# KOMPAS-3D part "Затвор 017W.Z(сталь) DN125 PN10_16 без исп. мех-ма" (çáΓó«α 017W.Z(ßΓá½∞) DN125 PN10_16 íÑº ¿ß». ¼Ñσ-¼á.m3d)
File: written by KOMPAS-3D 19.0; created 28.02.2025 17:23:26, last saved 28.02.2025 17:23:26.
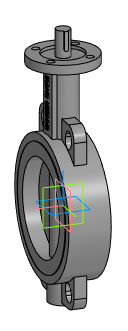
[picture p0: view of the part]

Document properties: Автор: Евгений; Полное имя файла: E:\Dendor Работа Сачек\3D для проекитирвщиков\1.5 Тип 017W.Z Сталь Затвор дисковый поворотный Межфланцевый\stp_Тип 017W.Z(сталь). Затвор без исполн. механизма\Затвор 017W.Z(сталь) DN125 PN10_16 без исп. мех-ма.m3d

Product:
- Part/product: Затвор 017W.Z(сталь) DN125 PN10_16 без исп. мех-ма

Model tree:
1. Операция без истории:1  (labels: Затвор 017W.Z(сталь) DN125 PN10_16 без исп. мех-ма)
